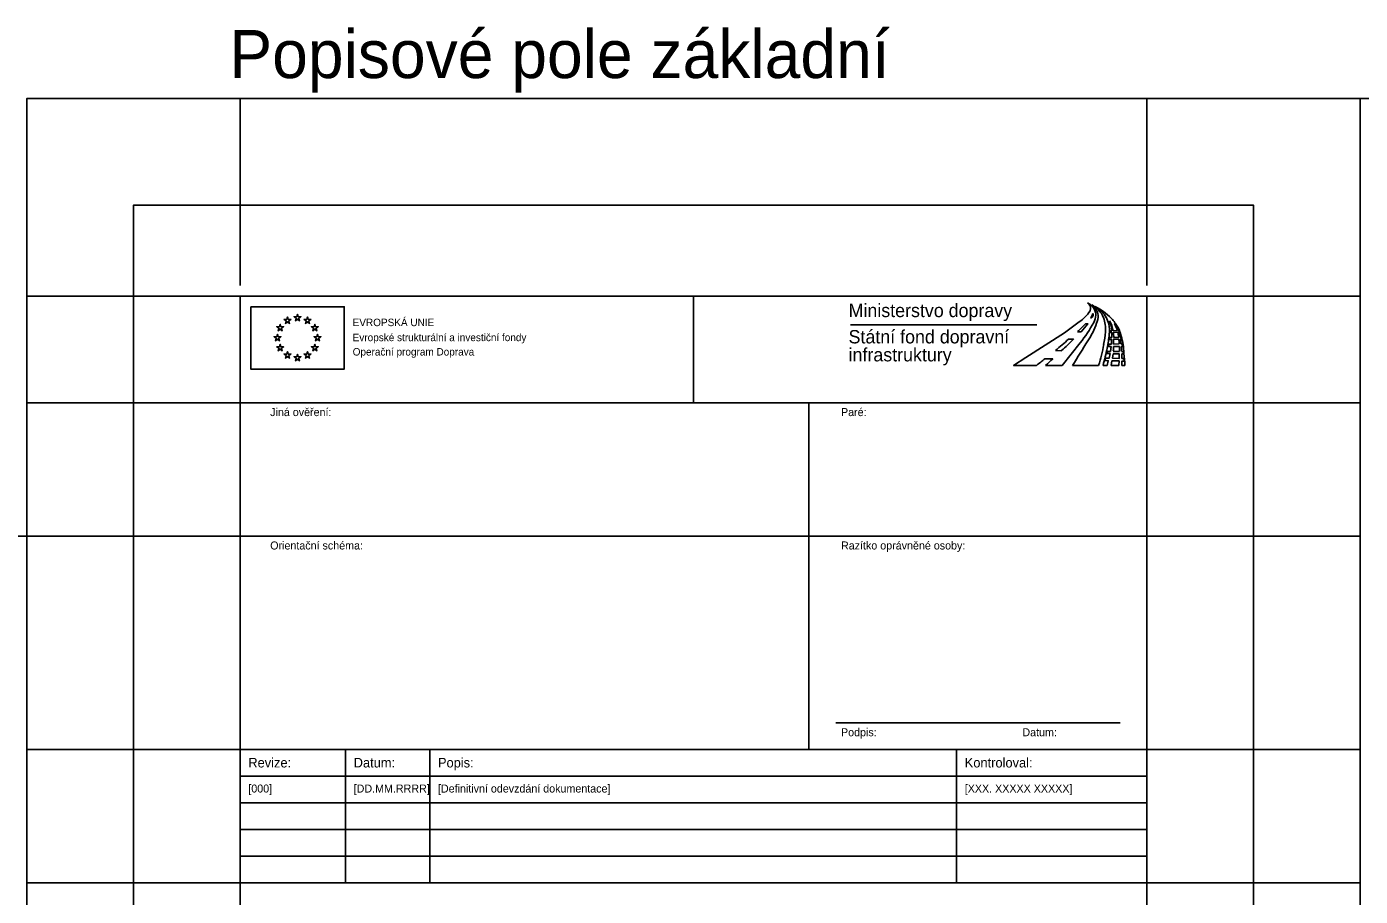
# Model space of a CAD drawing. Extents: x -34.3 to 48, y 36.7 to 71.8.
# Drawn here: x -2 to 23, y 55.48 to 71.78 of the extents above; entities that cross this region are included whole.
import ezdxf

# ---------------------------------------------------------------- set-up
doc = ezdxf.new("R2010")
doc.units = 0
for name, color, linetype in [('Default', 7, 'Continuous'), ('Rozpiska_Logo', 7, 'Continuous'), ('Rozpiska_pola_3', 7, 'Continuous'), ('Rozpiska_pole_1', 7, 'Continuous'), ('Rozpiska_pole_2', 7, 'Continuous'), ('Rozpiska_pole_4', 7, 'Continuous')]:
    doc.layers.add(name, color=color, linetype=linetype)

msp = doc.modelspace()

# ---------------------------------------------------------------- linework, layer by layer
at = {"layer": 'Default'}
for p, q in [((2, 66.934), (2, 70.434)), ((19, 66.934), (19, 70.434)), ((2, 66.734), (-2, 66.734)), ((10.5, 66.734), (10.5, 64.734)), ((19, 66.734), (23, 66.734)), ((-2, 64.734), (23, 64.734)), ((12.665, 58.234), (12.665, 64.734)), ((-27, 62.234), (-2, 62.234)), ((-2, 62.234), (23, 62.234)), ((-2, 58.234), (23, 58.234)), ((-2, 55.734), (23, 55.734))]:
    msp.add_line(p, q, dxfattribs=at)
for points in [[(-2, 36.734), (23, 36.734), (23, 70.434), (-2, 70.434)], [(23, 36.734), (48, 36.734), (48, 70.434), (23, 70.434)], [(0, 38.734), (21, 38.734), (21, 68.434), (0, 68.434)]]:
    msp.add_lwpolyline(points, close=True, dxfattribs=at)
at = {"layer": 'Rozpiska_Logo'}
for p, q in [((13.442, 66.196), (16.939, 66.196)), ((18.327, 65.434), (18.344, 65.517)), ((18.344, 65.517), (18.478, 65.517)), ((18.478, 65.517), (18.475, 65.433)), ((18.475, 65.433), (18.327, 65.434))]:
    msp.add_line(p, q, dxfattribs=at)
for points in [[(2.2, 66.534), (3.953, 66.534), (3.954, 65.365), (2.2, 65.365), (2.2, 66.534)], [(2.826, 66.295), (2.874, 66.295), (2.889, 66.341), (2.904, 66.295), (2.952, 66.295), (2.913, 66.267), (2.928, 66.221), (2.889, 66.249), (2.85, 66.221), (2.865, 66.267), (2.826, 66.295)], [(2.865, 66.267), (2.85, 66.221), (2.889, 66.249), (2.928, 66.221), (2.913, 66.267), (2.952, 66.295), (2.904, 66.295), (2.889, 66.341), (2.874, 66.295), (2.826, 66.295), (2.865, 66.267)], [(3.014, 66.345), (3.062, 66.345), (3.077, 66.391), (3.092, 66.345), (3.14, 66.345), (3.101, 66.317), (3.116, 66.271), (3.077, 66.3), (3.038, 66.271), (3.053, 66.317), (3.014, 66.345)], [(3.053, 66.317), (3.038, 66.271), (3.077, 66.3), (3.116, 66.271), (3.101, 66.317), (3.14, 66.345), (3.092, 66.345), (3.077, 66.391), (3.062, 66.345), (3.014, 66.345), (3.053, 66.317)], [(3.201, 66.295), (3.249, 66.295), (3.264, 66.341), (3.279, 66.295), (3.327, 66.295), (3.288, 66.267), (3.303, 66.221), (3.264, 66.249), (3.225, 66.221), (3.24, 66.267), (3.201, 66.295)], [(3.24, 66.267), (3.225, 66.221), (3.264, 66.249), (3.303, 66.221), (3.288, 66.267), (3.327, 66.295), (3.279, 66.295), (3.264, 66.341), (3.249, 66.295), (3.201, 66.295), (3.24, 66.267)], [(17.942, 66.323), (17.962, 66.323)], [(17.942, 66.323), (17.962, 66.323)], [(17.993, 66.398), (17.993, 66.398), (17.977, 66.398)], [(17.993, 66.398), (17.993, 66.398), (17.977, 66.398)], [(17.993, 66.398), (17.993, 66.398), (17.977, 66.398)], [(2.638, 65.97), (2.687, 65.97), (2.701, 66.016), (2.716, 65.97), (2.765, 65.97), (2.726, 65.942), (2.741, 65.896), (2.702, 65.924), (2.663, 65.896), (2.677, 65.942), (2.638, 65.97)], [(2.677, 65.942), (2.663, 65.896), (2.702, 65.924), (2.741, 65.896), (2.726, 65.942), (2.765, 65.97), (2.716, 65.97), (2.701, 66.016), (2.687, 65.97), (2.638, 65.97), (2.677, 65.942)], [(2.689, 66.158), (2.737, 66.158), (2.752, 66.204), (2.767, 66.158), (2.815, 66.158), (2.776, 66.129), (2.791, 66.084), (2.752, 66.112), (2.713, 66.084), (2.728, 66.129), (2.689, 66.158)], [(2.728, 66.129), (2.713, 66.084), (2.752, 66.112), (2.791, 66.084), (2.776, 66.129), (2.815, 66.158), (2.767, 66.158), (2.752, 66.204), (2.737, 66.158), (2.689, 66.158), (2.728, 66.129)], [(3.339, 66.158), (3.387, 66.158), (3.402, 66.204), (3.417, 66.158), (3.465, 66.158), (3.426, 66.129), (3.441, 66.084), (3.402, 66.112), (3.363, 66.084), (3.378, 66.129), (3.339, 66.158)], [(3.378, 66.129), (3.363, 66.084), (3.402, 66.112), (3.441, 66.084), (3.426, 66.129), (3.465, 66.158), (3.417, 66.158), (3.402, 66.204), (3.387, 66.158), (3.339, 66.158), (3.378, 66.129)], [(3.389, 65.97), (3.437, 65.97), (3.452, 66.016), (3.467, 65.97), (3.515, 65.97), (3.476, 65.942), (3.491, 65.896), (3.452, 65.924), (3.413, 65.896), (3.428, 65.942), (3.389, 65.97)], [(3.428, 65.942), (3.413, 65.896), (3.452, 65.924), (3.491, 65.896), (3.476, 65.942), (3.515, 65.97), (3.467, 65.97), (3.452, 66.016), (3.437, 65.97), (3.389, 65.97), (3.428, 65.942)], [(16.931, 65.434), (16.501, 65.434), (16.732, 65.585), (17.452, 66.044), (17.732, 66.249)], [(16.931, 65.434), (16.501, 65.434), (16.732, 65.585), (17.452, 66.044), (17.732, 66.249)], [(17.732, 66.249), (17.452, 66.044), (16.732, 65.585), (16.501, 65.434), (16.931, 65.434)], [(17.698, 66.066), (17.764, 66.066)], [(17.764, 66.066), (17.698, 66.066)], [(17.892, 66.211), (17.892, 66.211), (17.847, 66.212)], [(17.847, 66.212), (17.892, 66.211), (17.892, 66.211)], [(18.342, 66.081), (18.309, 66.079), (18.308, 66.048), (18.341, 66.051)], [(18.342, 66.081), (18.309, 66.079), (18.308, 66.048), (18.341, 66.051)], [(18.444, 66.087), (18.364, 66.082)], [(18.444, 66.087), (18.364, 66.082)], [(18.452, 66.06), (18.371, 66.053)], [(18.452, 66.06), (18.371, 66.053)], [(18.471, 66.062), (18.484, 66.062), (18.474, 66.089), (18.459, 66.088)], [(18.471, 66.062), (18.484, 66.062), (18.474, 66.089), (18.459, 66.088)], [(2.689, 65.782), (2.737, 65.782), (2.752, 65.828), (2.767, 65.782), (2.815, 65.782), (2.776, 65.754), (2.791, 65.708), (2.752, 65.737), (2.713, 65.708), (2.728, 65.754), (2.689, 65.782)], [(2.728, 65.754), (2.713, 65.708), (2.752, 65.737), (2.791, 65.708), (2.776, 65.754), (2.815, 65.782), (2.767, 65.782), (2.752, 65.828), (2.737, 65.782), (2.689, 65.782), (2.728, 65.754)], [(3.339, 65.783), (3.387, 65.783), (3.402, 65.828), (3.417, 65.783), (3.465, 65.783), (3.426, 65.754), (3.441, 65.708), (3.402, 65.737), (3.363, 65.708), (3.378, 65.754), (3.339, 65.783)], [(3.378, 65.754), (3.363, 65.708), (3.402, 65.737), (3.441, 65.708), (3.426, 65.754), (3.465, 65.783), (3.417, 65.783), (3.402, 65.828), (3.387, 65.783), (3.339, 65.783), (3.378, 65.754)], [(17.749, 65.858), (17.408, 65.434), (17.101, 65.434)], [(17.749, 65.858), (17.408, 65.434), (17.101, 65.434)], [(17.101, 65.434), (17.408, 65.434), (17.749, 65.858)], [(17.624, 65.925), (17.624, 65.925), (17.531, 65.925)], [(17.624, 65.925), (17.624, 65.925), (17.531, 65.925)], [(18.333, 65.832), (18.283, 65.83), (18.277, 65.787), (18.328, 65.788), (18.316, 65.697), (18.261, 65.697), (18.25, 65.656), (18.308, 65.655), (18.29, 65.569), (18.225, 65.57), (18.218, 65.523), (18.275, 65.522), (18.255, 65.434)], [(18.333, 65.832), (18.283, 65.83), (18.277, 65.787), (18.328, 65.788), (18.316, 65.697), (18.261, 65.697), (18.25, 65.656), (18.308, 65.655), (18.29, 65.569), (18.225, 65.57), (18.218, 65.523), (18.275, 65.522), (18.255, 65.434)], [(18.341, 65.957), (18.301, 65.954), (18.296, 65.919), (18.339, 65.921)], [(18.341, 65.957), (18.301, 65.954), (18.296, 65.919), (18.339, 65.921)], [(18.484, 65.79), (18.372, 65.788)], [(18.372, 65.788), (18.484, 65.79)], [(18.375, 65.834), (18.479, 65.838)], [(18.479, 65.838), (18.375, 65.834)], [(18.474, 65.927), (18.376, 65.923)], [(18.376, 65.923), (18.474, 65.927)], [(18.379, 65.959), (18.47, 65.964)], [(18.379, 65.959), (18.47, 65.964)], [(18.5, 65.928), (18.518, 65.929), (18.51, 65.966), (18.493, 65.965)], [(18.5, 65.928), (18.518, 65.929), (18.51, 65.966), (18.493, 65.965)], [(18.518, 65.791), (18.543, 65.791), (18.536, 65.84), (18.511, 65.839)], [(18.518, 65.791), (18.543, 65.791), (18.536, 65.84), (18.511, 65.839)], [(2.826, 65.645), (2.874, 65.645), (2.889, 65.691), (2.904, 65.645), (2.952, 65.645), (2.913, 65.617), (2.928, 65.571), (2.889, 65.599), (2.85, 65.571), (2.865, 65.617), (2.826, 65.645)], [(2.865, 65.617), (2.85, 65.571), (2.889, 65.599), (2.928, 65.571), (2.913, 65.617), (2.952, 65.645), (2.904, 65.645), (2.889, 65.691), (2.874, 65.645), (2.826, 65.645), (2.865, 65.617)], [(3.014, 65.595), (3.062, 65.595), (3.077, 65.641), (3.092, 65.595), (3.14, 65.595), (3.101, 65.567), (3.116, 65.521), (3.077, 65.549), (3.038, 65.521), (3.053, 65.567), (3.014, 65.595)], [(3.053, 65.567), (3.038, 65.521), (3.077, 65.549), (3.116, 65.521), (3.101, 65.567), (3.14, 65.595), (3.092, 65.595), (3.077, 65.641), (3.062, 65.595), (3.014, 65.595), (3.053, 65.567)], [(3.201, 65.645), (3.25, 65.645), (3.264, 65.691), (3.279, 65.645), (3.328, 65.645), (3.289, 65.617), (3.303, 65.571), (3.264, 65.599), (3.225, 65.571), (3.24, 65.617), (3.201, 65.645)], [(3.24, 65.617), (3.225, 65.571), (3.264, 65.599), (3.303, 65.571), (3.289, 65.617), (3.328, 65.645), (3.279, 65.645), (3.264, 65.691), (3.25, 65.645), (3.201, 65.645), (3.24, 65.617)], [(17.235, 65.555), (17.235, 65.555), (17.088, 65.56)], [(17.235, 65.555), (17.235, 65.555), (17.088, 65.56)], [(17.088, 65.56), (17.235, 65.555), (17.235, 65.555)], [(17.286, 65.716), (17.4, 65.71)], [(17.286, 65.716), (17.4, 65.71)], [(18.365, 65.651), (18.355, 65.567), (18.48, 65.564), (18.482, 65.65), (18.365, 65.651)], [(18.369, 65.697), (18.484, 65.697)], [(18.484, 65.697), (18.369, 65.697)], [(18.527, 65.652), (18.56, 65.652), (18.554, 65.697), (18.524, 65.697)], [(18.527, 65.652), (18.56, 65.652), (18.554, 65.697), (18.524, 65.697)], [(18.532, 65.434), (18.531, 65.515), (18.571, 65.514), (18.566, 65.562), (18.53, 65.563)], [(18.532, 65.434), (18.531, 65.515), (18.571, 65.514), (18.566, 65.562), (18.53, 65.563)], [(18.093, 65.434), (17.605, 65.434)], [(17.605, 65.434), (18.093, 65.434)], [(17.605, 65.434), (18.093, 65.434)], [(18.255, 65.434), (18.177, 65.434)], [(18.532, 65.434), (18.588, 65.434)], [(18.588, 65.434), (18.532, 65.434)]]:
    msp.add_lwpolyline(points, dxfattribs=at)
for centre, radius, start, end in [((17.829, 66.506), 0.116, 333.7821, 60.3253), ((17.764, 66.345), 0.289, 35.1291, 64.7751), ((17.829, 66.506), 0.116, 333.7821, 60.3253), ((17.764, 66.345), 0.289, 35.1291, 64.7751), ((17.764, 66.345), 0.289, 35.1291, 64.7751), ((17.829, 66.506), 0.116, 333.7821, 60.3253), ((17.659, 66.05), 0.605, 44.354, 59.6129), ((17.79, 66.328), 0.299, 8.8325, 54.3171), ((17.659, 66.05), 0.605, 44.354, 59.6129), ((17.79, 66.328), 0.299, 8.8325, 54.3171), ((17.659, 66.05), 0.605, 44.354, 59.6129), ((17.79, 66.328), 0.299, 8.8325, 54.3171), ((17.818, 66.383), 0.223, 358.3059, 35.1291), ((17.818, 66.383), 0.223, 358.3059, 35.1291), ((17.818, 66.383), 0.223, 358.3059, 35.1291), ((8.176, 53.759), 16.135, 51.8348, 52.3632), ((17.574, 65.626), 1.018, 55.8173, 63.4675), ((8.176, 53.759), 16.135, 51.8348, 52.3632), ((17.574, 65.626), 1.018, 55.8173, 63.4675), ((17.273, 66.901), 0.797, 305.1305, 325.9532), ((17.273, 66.901), 0.797, 305.1305, 325.9532), ((17.273, 66.901), 0.797, 305.1305, 325.9532), ((17.823, 66.425), 0.156, 319.6022, 350.325), ((17.823, 66.425), 0.156, 319.6022, 350.325), ((17.829, 66.422), 0.166, 323.7342, 351.8118), ((17.829, 66.422), 0.166, 323.7342, 351.8118), ((17.729, 66.386), 0.312, 331.1155, 358.3059), ((17.729, 66.386), 0.312, 331.1155, 358.3059), ((17.729, 66.386), 0.312, 331.1155, 358.3059), ((17.627, 66.382), 0.459, 339.6691, 359.0927), ((17.627, 66.382), 0.459, 339.6691, 359.0927), ((17.627, 66.382), 0.459, 339.6691, 359.0927), ((17.773, 66.165), 0.443, 21.6804, 44.0388), ((17.773, 66.165), 0.443, 21.6804, 44.0388), ((17.773, 66.165), 0.443, 21.6804, 44.0388), ((17.708, 65.743), 0.847, 45.7577, 58.8317), ((17.708, 65.743), 0.847, 45.7577, 58.8317), ((17.852, 66.118), 0.44, 29.5083, 48.0349), ((17.852, 66.118), 0.44, 29.5083, 48.0349), ((17.628, 66.116), 0.596, 354.8309, 20.9259), ((17.628, 66.116), 0.596, 354.8309, 20.9259), ((17.628, 66.116), 0.596, 354.8309, 20.9259), ((17.86, 66.118), 0.433, 12.5999, 30.087), ((17.86, 66.118), 0.433, 12.5999, 30.087), ((17.927, 66.028), 0.441, 6.9884, 33.3949), ((17.771, 66.042), 0.572, 3.8889, 23.6112), ((17.927, 66.028), 0.441, 6.9884, 33.3949), ((17.771, 66.042), 0.572, 3.8889, 23.6112), ((17.712, 65.735), 0.85, 32.4145, 46.3283), ((17.712, 65.735), 0.85, 32.4145, 46.3283), ((16.028, 67.926), 2.499, 311.9225, 316.7053), ((16.028, 67.926), 2.499, 311.9225, 316.7053), ((15.693, 67.51), 2.637, 321.2414, 331.1155), ((15.693, 67.51), 2.637, 321.2414, 331.1155), ((15.693, 67.51), 2.637, 321.2414, 331.1155), ((14.243, 69.317), 4.793, 317.2846, 319.5966), ((14.243, 69.317), 4.793, 317.2846, 319.5966), ((16.559, 66.778), 1.598, 326.3997, 339.6645), ((16.559, 66.778), 1.598, 326.3997, 339.6645), ((16.559, 66.778), 1.598, 326.3997, 339.6645), ((16.549, 66.17), 1.676, 348.0644, 356.2998), ((16.549, 66.17), 1.676, 348.0644, 356.2998), ((16.549, 66.17), 1.676, 348.0644, 356.2998), ((16.258, 66.178), 2.04, 348.131, 355.4957), ((16.258, 66.178), 2.04, 348.131, 355.4957), ((17.828, 66.093), 0.47, 350.7277, 14.6627), ((17.828, 66.093), 0.47, 350.7277, 14.6627), ((17.178, 66.001), 1.164, 357.822, 2.4688), ((17.178, 66.001), 1.164, 357.822, 2.4688), ((17.422, 65.927), 0.957, 1.9262, 7.6145), ((17.422, 65.927), 0.957, 1.9262, 7.6145), ((17.949, 65.911), 0.539, 19.1508, 35.05), ((17.292, 65.708), 1.213, 18.2045, 25.0006), ((17.949, 65.911), 0.539, 19.1508, 35.05), ((17.292, 65.708), 1.213, 18.2045, 25.0006), ((17.901, 65.837), 0.636, 13.4543, 33.7828), ((17.901, 65.837), 0.636, 13.4543, 33.7828), ((17.662, 65.861), 0.815, 7.2316, 14.102), ((17.662, 65.861), 0.815, 7.2316, 14.102), ((17.89, 65.877), 0.61, 8.3249, 17.6578), ((17.89, 65.877), 0.61, 8.3249, 17.6578), ((12.238, 71.863), 7.955, 309.3914, 311.7102), ((12.238, 71.863), 7.955, 309.3914, 311.7102), ((13.573, 69.907), 5.68, 312.3671, 315.4937), ((13.573, 69.907), 5.68, 312.3671, 315.4937), ((-22.272, 90.518), 47.111, 327.8282, 328.4861), ((-22.272, 90.518), 47.111, 327.8282, 328.4861), ((-22.272, 90.518), 47.111, 327.8282, 328.4861), ((15.385, 66.308), 2.846, 342.1151, 350.2059), ((15.385, 66.308), 2.846, 342.1151, 350.2059), ((15.385, 66.308), 2.846, 342.1151, 350.2059), ((15.032, 66.363), 3.279, 343.5415, 349.3721), ((15.032, 66.363), 3.279, 343.5415, 349.3721), ((20.202, 65.755), 1.871, 174.904, 177.6286), ((20.202, 65.755), 1.871, 174.904, 177.6286), ((17.831, 65.764), 0.541, 352.9784, 2.6252), ((17.831, 65.764), 0.541, 352.9784, 2.6252), ((13.148, 65.934), 5.228, 358.9091, 359.8809), ((13.148, 65.934), 5.228, 358.9091, 359.8809), ((16.537, 65.771), 1.943, 1.988, 4.6084), ((16.537, 65.771), 1.943, 1.988, 4.6084), ((17.853, 65.748), 0.633, 355.4573, 3.8566), ((17.853, 65.748), 0.633, 355.4573, 3.8566), ((18.122, 65.839), 0.388, 0.0904, 13.2769), ((18.122, 65.839), 0.388, 0.0904, 13.2769), ((17.454, 65.672), 1.071, 1.3852, 6.3824), ((17.454, 65.672), 1.071, 1.3852, 6.3824), ((16.946, 65.58), 1.625, 2.7985, 14.4251), ((16.946, 65.58), 1.625, 2.7985, 14.4251), ((19.107, 62.896), 3.342, 127.1682, 130.6153), ((19.107, 62.896), 3.342, 127.1682, 130.6153), ((19.107, 62.896), 3.342, 127.1682, 130.6153), ((18.951, 63.54), 2.647, 130.4231, 134.3309), ((18.951, 63.54), 2.647, 130.4231, 134.3309), ((18.951, 63.54), 2.647, 130.4231, 134.3309), ((14.589, 65.482), 3.942, 1.1818, 2.4809), ((14.589, 65.482), 3.942, 1.1818, 2.4809), ((15.29, 65.276), 3.301, 2.7322, 6.6695), ((15.29, 65.276), 3.301, 2.7322, 6.6695)]:
    msp.add_arc(centre, radius, start, end, dxfattribs=at)
at = {"layer": 'Rozpiska_pola_3'}
msp.add_line((13.165, 58.734), (18.5, 58.734), dxfattribs=at)
at = {"layer": 'Rozpiska_pole_1'}
msp.add_lwpolyline([(2, 66.734), (19, 66.734), (19, 40.234), (2, 40.234)], close=True, dxfattribs=at)
at = {"layer": 'Rozpiska_pole_2'}
for points in [[(2, 64.734), (12.665, 64.734), (12.665, 62.234), (2, 62.234)], [(12.665, 64.734), (19, 64.734), (19, 62.234), (12.665, 62.234)], [(2, 62.234), (12.665, 62.234), (12.665, 58.234), (2, 58.234)], [(19, 62.234), (12.665, 62.234), (12.665, 58.234), (19, 58.234)]]:
    msp.add_lwpolyline(points, close=True, dxfattribs=at)
at = {"layer": 'Rozpiska_pole_4'}
for p, q in [((3.975, 55.734), (3.975, 58.234)), ((5.555, 55.734), (5.555, 58.234)), ((15.43, 55.734), (15.43, 58.234)), ((2, 57.734), (19, 57.734)), ((2, 57.234), (19, 57.234)), ((2, 56.734), (19, 56.734)), ((2, 56.234), (19, 56.234))]:
    msp.add_line(p, q, dxfattribs=at)
msp.add_lwpolyline([(2, 58.234), (19, 58.234), (19, 55.734), (2, 55.734)], close=True, dxfattribs=at)

# ---------------------------------------------------------------- texts
at = {"layer": 'Default'}
msp.add_text('Popisové pole základní', height=0.9, dxfattribs=at).set_placement((1.799, 70.819))
at = {"layer": 'Rozpiska_Logo'}
for s, height, p in [('Ministerstvo dopravy', 0.25, (13.407, 66.339)), ('EVROPSKÁ UNIE', 0.14, (4.111, 66.17)), ('Evropské strukturální a investiční fondy', 0.14, (4.111, 65.888)), ('Státní fond dopravní', 0.25, (13.407, 65.846)), ('Operační program Doprava', 0.14, (4.111, 65.619)), ('infrastruktury', 0.25, (13.407, 65.509))]:
    msp.add_text(s, height=height, rotation=0.0062, dxfattribs=at).set_placement(p)
at = {"layer": 'Rozpiska_pola_3'}
for s, p in [('Paré:', (13.265, 64.484)), ('Razítko oprávněné osoby:', (13.265, 61.984)), ('Podpis:', (13.265, 58.484)), ('Datum:', (16.665, 58.484))]:
    msp.add_text(s, height=0.15, dxfattribs=at).set_placement(p)
at = {"layer": 'Rozpiska_pole_2'}
for s, p in [('Jiná ověření:', (2.565, 64.484)), ('Orientační schéma:', (2.565, 61.984))]:
    msp.add_text(s, height=0.15, dxfattribs=at).set_placement(p)
at = {"layer": 'Rozpiska_pole_4'}
for s, height, p in [('Revize:', 0.18, (2.155, 57.899)), ('Datum:', 0.18, (4.13, 57.899)), ('Popis:', 0.18, (5.71, 57.899)), ('Kontroloval:', 0.18, (15.585, 57.899)), ('[000]', 0.15, (2.155, 57.429)), ('[DD.MM.RRRR]', 0.15, (4.13, 57.429)), ('[Definitivní odevzdání dokumentace]', 0.15, (5.71, 57.429)), ('[XXX. XXXXX XXXXX]', 0.15, (15.585, 57.429))]:
    msp.add_text(s, height=height, dxfattribs=at).set_placement(p)

doc.saveas('drawing.dxf')
